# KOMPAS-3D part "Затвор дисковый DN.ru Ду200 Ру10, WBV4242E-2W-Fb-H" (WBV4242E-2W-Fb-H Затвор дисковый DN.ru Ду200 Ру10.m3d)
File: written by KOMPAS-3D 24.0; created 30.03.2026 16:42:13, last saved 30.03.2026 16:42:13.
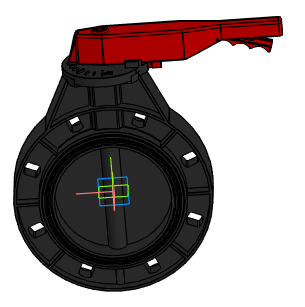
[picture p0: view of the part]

Document properties: Автор: R2D2; Полное имя файла: E:\Работа\Зайцев\WBV4242E-2W-Fb-H Затвор дисковый DN.ru Ду50-200 Ру10\DN200\WBV4242E-2W-Fb-H Затвор дисковый DN.ru Ду200 Ру10.m3d

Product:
- Part/product: Затвор дисковый DN.ru Ду200 Ру10  | designation WBV4242E-2W-Fb-H
    Масса: 7.97
    Раздел спецификации: Прочие изделия
    Примечание: D050-81203

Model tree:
1. Операция без истории:1

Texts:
  WBV4242E-2W-Fb-H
